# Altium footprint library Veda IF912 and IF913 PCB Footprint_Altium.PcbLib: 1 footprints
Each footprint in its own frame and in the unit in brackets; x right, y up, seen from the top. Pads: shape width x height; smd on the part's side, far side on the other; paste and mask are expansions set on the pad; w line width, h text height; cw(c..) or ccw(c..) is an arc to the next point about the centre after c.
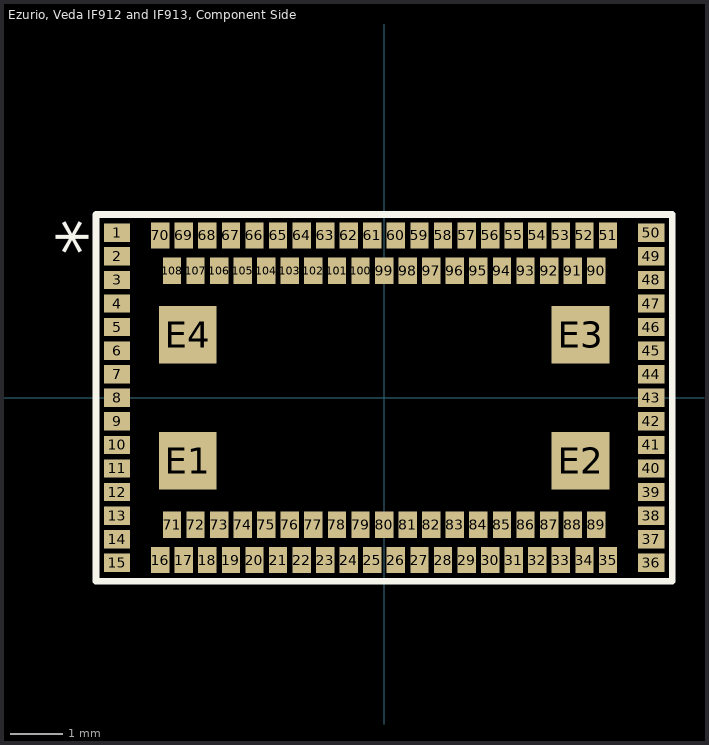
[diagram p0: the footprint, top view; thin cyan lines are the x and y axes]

## Ezurio, Veda IF912 and IF913, Component Side [mm] "Ezurio, Veda IF912 and IF913, Component Side"
height 1.4
pads (112):
  rect 0.5x0.35 smd paste-0.05 mask-0.05: 1(-5.1,3.15) 2(-5.1,2.7) 3(-5.1,2.25) 4(-5.1,1.8) 5(-5.1,1.35) 6(-5.1,0.9) 7(-5.1,0.45) 8(-5.1,0) 9(-5.1,-0.45) 10(-5.1,-0.9) 11(-5.1,-1.35) 12(-5.1,-1.8) 13(-5.1,-2.25) 14(-5.1,-2.7) 15(-5.1,-3.15) 36(5.1,-3.15) 37(5.1,-2.7) 38(5.1,-2.25) 39(5.1,-1.8) 40(5.1,-1.35) 41(5.1,-0.9) 42(5.1,-0.45) 43(5.1,0) 44(5.1,0.45) 45(5.1,0.9) 46(5.1,1.35) 47(5.1,1.8) 48(5.1,2.25) 49(5.1,2.7) 50(5.1,3.15)
  rect 0.35x0.5 smd paste-0.05 mask-0.05: 16(-4.275,-3.1) 17(-3.825,-3.1) 18(-3.375,-3.1) 19(-2.925,-3.1) 20(-2.475,-3.1) 21(-2.025,-3.1) 22(-1.575,-3.1) 23(-1.125,-3.1) 24(-0.675,-3.1) 25(-0.225,-3.1) 26(0.225,-3.1) 27(0.675,-3.1) 28(1.125,-3.1) 29(1.575,-3.1) 30(2.025,-3.1) 31(2.475,-3.1) 32(2.925,-3.1) 33(3.375,-3.1) 34(3.825,-3.1) 35(4.275,-3.1) 51(4.275,3.1) 52(3.825,3.1) 53(3.375,3.1) 54(2.925,3.1) 55(2.475,3.1) 56(2.025,3.1) 57(1.575,3.1) 58(1.125,3.1) 59(0.675,3.1) 60(0.225,3.1) 61(-0.225,3.1) 62(-0.675,3.1) 63(-1.125,3.1) 64(-1.575,3.1) 65(-2.025,3.1) 66(-2.475,3.1) 67(-2.925,3.1) 68(-3.375,3.1) 69(-3.825,3.1) 70(-4.275,3.1) 71(-4.05,-2.425) 72(-3.6,-2.425) 73(-3.15,-2.425) 74(-2.7,-2.425) 75(-2.25,-2.425) 76(-1.8,-2.425) 77(-1.35,-2.425) 78(-0.9,-2.425) 79(-0.45,-2.425) 80(0,-2.425) 81(0.45,-2.425) 82(0.9,-2.425) 83(1.35,-2.425) 84(1.8,-2.425) 85(2.25,-2.425) 86(2.7,-2.425) 87(3.15,-2.425) 88(3.6,-2.425) 89(4.05,-2.425) 90(4.05,2.425) 91(3.6,2.425) 92(3.15,2.425) 93(2.7,2.425) 94(2.25,2.425) 95(1.8,2.425) 96(1.35,2.425) 97(0.9,2.425) 98(0.45,2.425) 99(0,2.425) 100(-0.45,2.425) 101(-0.9,2.425) 102(-1.35,2.425) 103(-1.8,2.425) 104(-2.25,2.425) 105(-2.7,2.425) 106(-3.15,2.425) 107(-3.6,2.425) 108(-4.05,2.425)
  rect 1.1x1.1 smd paste-0.05 mask-0.05: E1(-3.75,-1.2) E2(3.75,-1.2) E3(3.75,1.2) E4(-3.75,1.2)
Top Overlay:
  lines w0.127: -5.5,-3.5 5.5,-3.5 5.5,3.5 -5.5,3.5 -5.5,-3.5
  text "*" at -6.65,3.408 h1
Top Assembly:
  lines w0.025: -5.5,-3.5 5.5,-3.5 5.5,3.5 -5.5,3.5 -5.5,-3.5
  text "*" at -6.652,3.41 h1
  text ".Designator" at -5.719,4.334 h0.76
3D body: height 0.01, standoff 0, extent -5.3,3.025 -4.9,3.275
3D body: height 0.01, standoff 0, extent -5.3,2.575 -4.9,2.825
3D body: height 0.01, standoff 0, extent -5.3,2.125 -4.9,2.375
3D body: height 0.01, standoff 0, extent -5.3,1.675 -4.9,1.925
3D body: height 0.01, standoff 0, extent -5.3,1.225 -4.9,1.475
3D body: height 0.01, standoff 0, extent -5.3,0.775 -4.9,1.025
3D body: height 0.01, standoff 0, extent -5.3,0.325 -4.9,0.575
3D body: height 0.01, standoff 0, extent -5.3,-0.125 -4.9,0.125
3D body: height 0.01, standoff 0, extent -5.3,-0.575 -4.9,-0.325
3D body: height 0.01, standoff 0, extent -5.3,-1.025 -4.9,-0.775
3D body: height 0.01, standoff 0, extent -5.3,-1.475 -4.9,-1.225
3D body: height 0.01, standoff 0, extent -5.3,-1.925 -4.9,-1.675
3D body: height 0.01, standoff 0, extent -5.3,-2.375 -4.9,-2.125
3D body: height 0.01, standoff 0, extent -5.3,-2.825 -4.9,-2.575
3D body: height 0.01, standoff 0, extent -5.3,-3.275 -4.9,-3.025
3D body: height 0.01, standoff 0, extent -4.4,2.9 -4.15,3.3
3D body: height 0.01, standoff 0, extent -3.95,2.9 -3.7,3.3
3D body: height 0.01, standoff 0, extent -3.5,2.9 -3.25,3.3
3D body: height 0.01, standoff 0, extent -3.05,2.9 -2.8,3.3
3D body: height 0.01, standoff 0, extent -2.6,2.9 -2.35,3.3
3D body: height 0.01, standoff 0, extent -2.15,2.9 -1.9,3.3
3D body: height 0.01, standoff 0, extent -1.7,2.9 -1.45,3.3
3D body: height 0.01, standoff 0, extent -1.25,2.9 -1,3.3
3D body: height 0.01, standoff 0, extent -0.8,2.9 -0.55,3.3
3D body: height 0.01, standoff 0, extent -0.35,2.9 -0.1,3.3
3D body: height 0.01, standoff 0, extent 0.1,2.9 0.35,3.3
3D body: height 0.01, standoff 0, extent 0.55,2.9 0.8,3.3
3D body: height 0.01, standoff 0, extent 1,2.9 1.25,3.3
3D body: height 0.01, standoff 0, extent 1.45,2.9 1.7,3.3
3D body: height 0.01, standoff 0, extent 1.9,2.9 2.15,3.3
3D body: height 0.01, standoff 0, extent -4.175,2.225 -3.925,2.625
3D body: height 0.01, standoff 0, extent -3.725,2.225 -3.475,2.625
3D body: height 0.01, standoff 0, extent -3.275,2.225 -3.025,2.625
3D body: height 0.01, standoff 0, extent -2.825,2.225 -2.575,2.625
3D body: height 0.01, standoff 0, extent -2.375,2.225 -2.125,2.625
3D body: height 0.01, standoff 0, extent -1.925,2.225 -1.675,2.625
3D body: height 0.01, standoff 0, extent -1.475,2.225 -1.225,2.625
3D body: height 0.01, standoff 0, extent -1.025,2.225 -0.775,2.625
3D body: height 0.01, standoff 0, extent -0.575,2.225 -0.325,2.625
3D body: height 0.01, standoff 0, extent -0.125,2.225 0.125,2.625
3D body: height 0.01, standoff 0, extent 0.325,2.225 0.575,2.625
3D body: height 0.01, standoff 0, extent 0.775,2.225 1.025,2.625
3D body: height 0.01, standoff 0, extent 1.225,2.225 1.475,2.625
3D body: height 0.01, standoff 0, extent 1.675,2.225 1.925,2.625
3D body: height 0.01, standoff 0, extent 2.125,2.225 2.375,2.625
3D body: height 0.01, standoff 0, extent 4.9,3.025 5.3,3.275
3D body: height 0.01, standoff 0, extent 4.9,2.575 5.3,2.825
3D body: height 0.01, standoff 0, extent 4.9,2.125 5.3,2.375
3D body: height 0.01, standoff 0, extent 4.9,1.675 5.3,1.925
3D body: height 0.01, standoff 0, extent 4.9,1.225 5.3,1.475
3D body: height 0.01, standoff 0, extent 4.9,0.775 5.3,1.025
3D body: height 0.01, standoff 0, extent 4.9,0.325 5.3,0.575
3D body: height 0.01, standoff 0, extent 4.9,-0.125 5.3,0.125
3D body: height 0.01, standoff 0, extent 4.9,-0.575 5.3,-0.325
3D body: height 0.01, standoff 0, extent 4.9,-1.025 5.3,-0.775
3D body: height 0.01, standoff 0, extent 4.9,-1.475 5.3,-1.225
3D body: height 0.01, standoff 0, extent 4.9,-1.925 5.3,-1.675
3D body: height 0.01, standoff 0, extent 4.9,-2.375 5.3,-2.125
3D body: height 0.01, standoff 0, extent 4.9,-2.825 5.3,-2.575
3D body: height 0.01, standoff 0, extent 4.9,-3.275 5.3,-3.025
3D body: height 0.01, standoff 0, extent -4.4,-3.3 -4.15,-2.9
3D body: height 0.01, standoff 0, extent -3.95,-3.3 -3.7,-2.9
3D body: height 0.01, standoff 0, extent -3.5,-3.3 -3.25,-2.9
3D body: height 0.01, standoff 0, extent -3.05,-3.3 -2.8,-2.9
3D body: height 0.01, standoff 0, extent -2.6,-3.3 -2.35,-2.9
3D body: height 0.01, standoff 0, extent -2.15,-3.3 -1.9,-2.9
3D body: height 0.01, standoff 0, extent -1.7,-3.3 -1.45,-2.9
3D body: height 0.01, standoff 0, extent -1.25,-3.3 -1,-2.9
3D body: height 0.01, standoff 0, extent -0.8,-3.3 -0.55,-2.9
3D body: height 0.01, standoff 0, extent -0.35,-3.3 -0.1,-2.9
3D body: height 0.01, standoff 0, extent 0.1,-3.3 0.35,-2.9
3D body: height 0.01, standoff 0, extent 0.55,-3.3 0.8,-2.9
3D body: height 0.01, standoff 0, extent 1,-3.3 1.25,-2.9
3D body: height 0.01, standoff 0, extent 1.45,-3.3 1.7,-2.9
3D body: height 0.01, standoff 0, extent 1.9,-3.3 2.15,-2.9
3D body: height 0.01, standoff 0, extent -4.175,-2.625 -3.925,-2.225
3D body: height 0.01, standoff 0, extent -3.725,-2.625 -3.475,-2.225
3D body: height 0.01, standoff 0, extent -3.275,-2.625 -3.025,-2.225
3D body: height 0.01, standoff 0, extent -2.825,-2.625 -2.575,-2.225
3D body: height 0.01, standoff 0, extent -2.375,-2.625 -2.125,-2.225
3D body: height 0.01, standoff 0, extent -1.925,-2.625 -1.675,-2.225
3D body: height 0.01, standoff 0, extent -1.475,-2.625 -1.225,-2.225
3D body: height 0.01, standoff 0, extent -1.025,-2.625 -0.775,-2.225
3D body: height 0.01, standoff 0, extent -0.575,-2.625 -0.325,-2.225
3D body: height 0.01, standoff 0, extent -0.125,-2.625 0.125,-2.225
3D body: height 0.01, standoff 0, extent 0.325,-2.625 0.575,-2.225
3D body: height 0.01, standoff 0, extent 0.775,-2.625 1.025,-2.225
3D body: height 0.01, standoff 0, extent 1.225,-2.625 1.475,-2.225
3D body: height 0.01, standoff 0, extent 1.675,-2.625 1.925,-2.225
3D body: height 0.01, standoff 0, extent 2.125,-2.625 2.375,-2.225
3D body: height 0.01, standoff 0, extent 2.575,-2.625 2.825,-2.225
3D body: height 0.01, standoff 0, extent 3.025,-2.625 3.275,-2.225
3D body: height 0.01, standoff 0, extent 3.475,-2.625 3.725,-2.225
3D body: height 0.01, standoff 0, extent 3.925,-2.625 4.175,-2.225
3D body: height 0.01, standoff 0, extent 2.35,-3.3 2.6,-2.9
3D body: height 0.01, standoff 0, extent 2.8,-3.3 3.05,-2.9
3D body: height 0.01, standoff 0, extent 3.25,-3.3 3.5,-2.9
3D body: height 0.01, standoff 0, extent 3.7,-3.3 3.95,-2.9
3D body: height 0.01, standoff 0, extent 2.35,2.9 2.6,3.3
3D body: height 0.01, standoff 0, extent 2.8,2.9 3.05,3.3
3D body: height 0.01, standoff 0, extent 3.25,2.9 3.5,3.3
3D body: height 0.01, standoff 0, extent 3.7,2.9 3.95,3.3
3D body: height 0.01, standoff 0, extent 2.575,2.225 2.825,2.625
3D body: height 0.01, standoff 0, extent 3.025,2.225 3.275,2.625
3D body: height 0.01, standoff 0, extent 3.475,2.225 3.725,2.625
3D body: height 0.01, standoff 0, extent 3.925,2.225 4.175,2.625
3D body: height 0.01, standoff 0, extent 4.15,2.9 4.4,3.3
3D body: height 0.01, standoff 0, extent 4.15,-3.3 4.4,-2.9
3D body: height 0.01, standoff 0, extent 3.25,-1.7 4.25,-0.7
3D body: height 0.01, standoff 0, extent 3.25,0.7 4.25,1.7
3D body: height 0.01, standoff 0, extent -4.25,0.7 -3.25,1.7
3D body: height 0.01, standoff 0, extent -4.25,-1.7 -3.25,-0.7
